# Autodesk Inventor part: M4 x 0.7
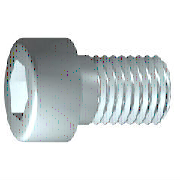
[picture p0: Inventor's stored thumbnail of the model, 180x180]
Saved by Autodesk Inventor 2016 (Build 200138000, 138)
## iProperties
IsCustomPart: 0
Created: 2015-10
Part Number: M4 x 0.7
Material: Steel, Mild
Description: 6각머리 태핑 나사
Document SubType Name: Modeling
Standard: KS B 1003
Designer: mdu
Standards Organization: KS
Language: ko-KR
Size Designation: M 4 x 25
Categories: <MemberInstance><Categories><Category DisplayName="조임쇠" InternalName="e4da775c-781d-43d5-af7c-5136215cf5a6" Mnemonic="FSTN"><Category DisplayName="볼트" InternalN
Density: 1 g/cm^3
Appearance: Steel
Author: mdu
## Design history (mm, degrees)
revolve "본체" stored, may be unused: angle "d10" = 90 deg
sketch "스케치2"
  geometry: L1 (0, -4.9)-(0, 4.9) reference; L2 (-4.9, 0)-(4.9, 0) reference; L3 (1.732, 0)-(0.866, -1.5); L4 (0.866, -1.5)-(-0.866, -1.5); L5 (-0.866, -1.5)-(-1.732, 0); L6 (-1.732, 0)-(-0.866, 1.5); L7 (-0.866, 1.5)-(0.866, 1.5); L8 (0.866, 1.5)-(1.732, 0); 2 further points
  constraints: 12 end point, 1 coincident, 1 horizontal alignment, 1 point on line, 12 other
extrude "슬롯" join sketch "스케치2" stored distance "d11" = 10; taper "d12" = 0 deg
workplane "Work Plane1"
fillet "Fillet2" dims "d30" = 0.1 (= R)
body "Solid1"
fillet "모깎기1" dims "d17" = 0.4 (= RR)
feature "스레드" dims "d13" = 23.25 (= GEL), "d14" = 0
chamfer "모따기1" distance "d15" = 0.42941 (= -0.5 x SPD + 0.5 x GD); stored, may be unused: second distance "d16" = 0.42941 (= GUL), angle "d27" = 45 deg
sketch "스케치1"
  geometry: L1 (-1, 0)-(25, 0); L2 (25, 0)-(25, 2); L3 (25, 2)-(1.75, 2); L4 (1.75, 2)-(1.32, 2); L5 (1.32, 2)-(0, 2); L6 (0, 2)-(0, 3.5); L7 (0, 3.5)-(-4, 3.5); L8 (-4, 3.5)-(-4, 1.732); L9 (-4, 1.732)-(-2, 1.732); L10 (-2, 1.732)-(-1, 0); L11 (-9.8, 0)-(30.8, 0) reference; L12 (0, -0.7)-(0, 4.2) reference; L13 (1.75, 2)-(0, 2)
  constraints: 22 end point, 6 parallel, 2 collinear, 2 perpendicular, 1 horizontal, 1 point on line
  dimensions: "d1" = 23.25 distance from line of L3.end L2 (= GEL); "d2" = 0.42952 distance of L4.end L3.end (computed from GAL); "d3" = 4 distance between parallel lines of L8 L6 (= KOH); "d4" = 2 distance of L8.end L9.end (= INTI); "d5" = 60 deg angle of L10 L1; "d6" = 4 diameter of L3 L1 (= GD); "d7" = 4 diameter of L5 L1 (= BDM); "d8" = 3.4641 diameter of L9 L1 (= 1.1547 x SW); "d9" = 7 diameter of L7 L1 (= KOD); "d26" = 25 distance between parallel lines of L12 L2 (= NLG)
other parameters: "GD" = 4 (= NND) [user parameter; used in 2 equation terms], "NLG" = 25 [user parameter; used in 1 equation term], "GEL" = 23.25 [user parameter; used in 2 equation terms], "KOD" = 7 [user parameter; used in 1 equation term], "KOH" = 4 [user parameter; used in 1 equation term], "INTI" = 2 [user parameter; used in 1 equation term], "GAL" = 0.42941 (= 0.61345 x PTC) [user parameter; used in 1 equation term], "GUL" = 0.42941 (= 0.61345 x PTC) [user parameter; used in 1 equation term], "BDM" = 4 (= NND) [user parameter; used in 1 equation term], "SW" = 3 [user parameter; used in 2 equation terms], "RR" = 0.4 [user parameter; used in 1 equation term], "SPD" = 3.14117 (= NND - 1.2269 x PTC) [user parameter; used in 1 equation term], "d19" = 0, "d28" = 0, "d29" = 0, "R" = 0.1 [user parameter; used in 1 equation term], "PHH" = 0.2 [user parameter], "GD1" = 3.14117 (= THREADDIA - 1.2269 x PTC) [user parameter], "THREADDIA" = 4 [user parameter; used in 1 equation term], "FAWI" = 45 deg [user parameter], "TPU" = 14.28571 (computed from PTC) [user parameter], "PTC" = 0.7 [user parameter; used in 5 equation terms], "NND" = 4 [user parameter; used in 3 equation terms], "TOA" = 30 deg [user parameter], "E0" = 3.465 (= 1.155 x SW) [user parameter]
